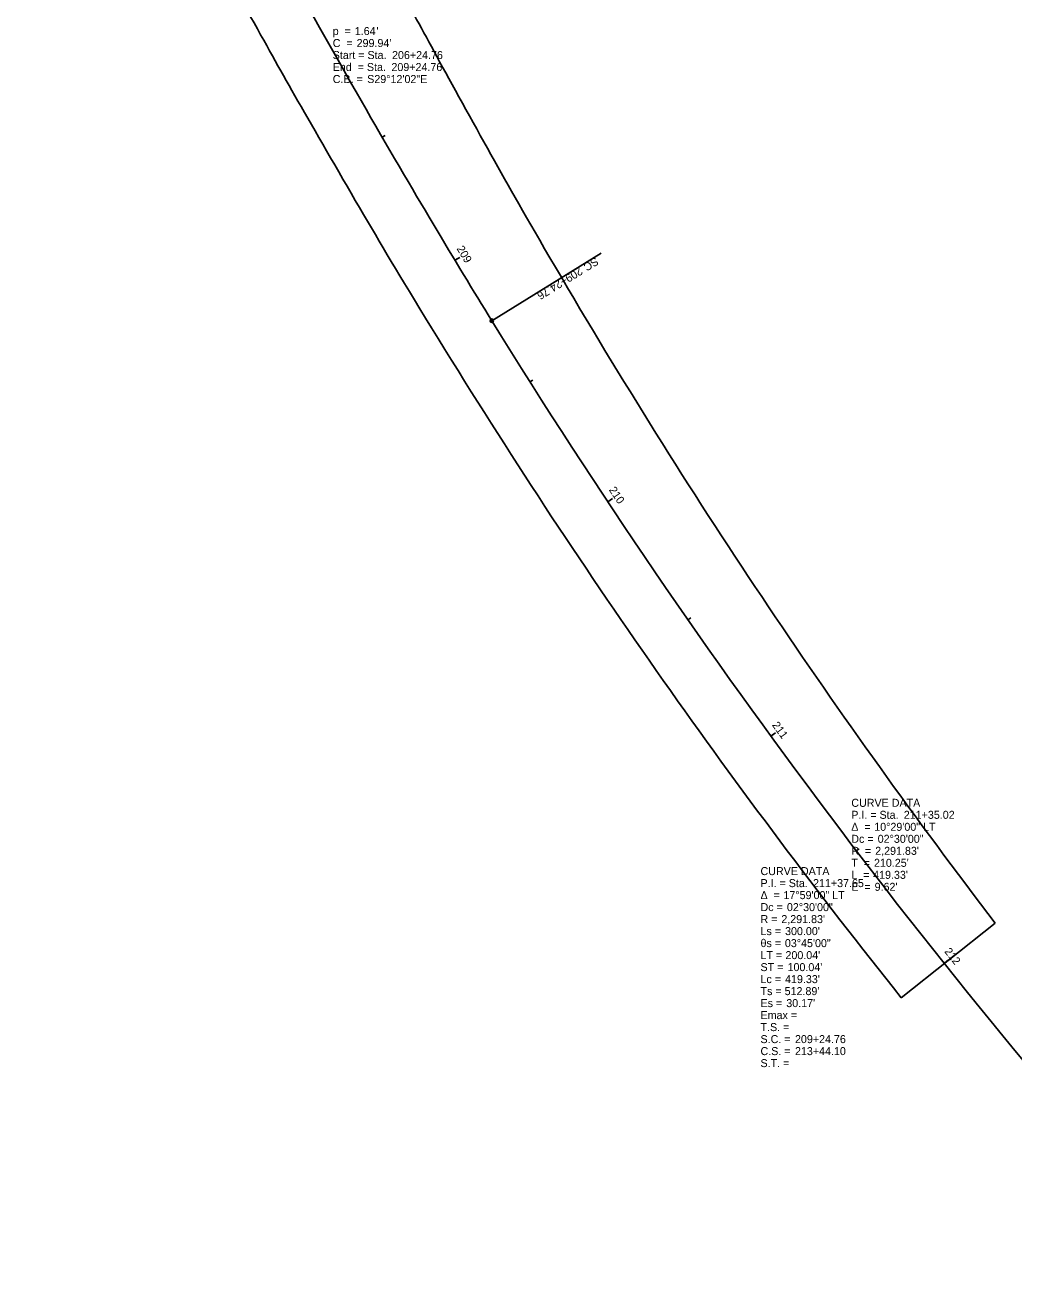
# Model space of a CAD drawing. Extents: x 2297881 to 2300632, y 559916 to 564460.
# Drawn here: x 2299974.2 to 2300320.3, y 560130.3 to 560568.5 of the extents above; entities that cross this region are included whole.
import ezdxf

# ---------------------------------------------------------------- set-up
doc = ezdxf.new("R2010")
doc.units = 0
for name, color, linetype in [('DT_P_Tie', 7, 'Continuous'), ('GE_X_Alignment', 7, 'Continuous'), ('GE_X_Alignment_1000_Cardinal_Points', 7, 'Continuous'), ('GE_X_Alignment_1000_Curve_Data', 7, 'Continuous'), ('GE_X_Alignment_1000_Stations', 7, 'Continuous'), ('GE_X_Alignment_100_Cardinal_Points', 7, 'Continuous'), ('GE_X_Alignment_100_Curve_Data', 7, 'Continuous'), ('GE_X_Alignment_100_Stations', 7, 'Continuous'), ('GE_X_Alignment_500_Cardinal_Points', 7, 'Continuous'), ('GE_X_Alignment_500_Curve_Data', 7, 'Continuous'), ('GE_X_Alignment_500_Stations', 7, 'Continuous')]:
    doc.layers.add(name, color=color, linetype=linetype)

msp = doc.modelspace()

# ---------------------------------------------------------------- linework, layer by layer
at = {"layer": 'DT_P_Tie'}
msp.add_line((2300280.82, 560228.09), (2300313.72, 560254.2), dxfattribs=at)
for centre, radius, start, end in [((2302108.04, 561623.44), 2257.08, 210.43127, 217.34714), ((2302087.44, 561669.34), 2311.08, 211.7005, 218.58141)]:
    msp.add_arc(centre, radius, start, end, dxfattribs=at)
for points in [[(2300033.82, 560720.69), (2300044.1, 560700.26), (2300054.38, 560679.88), (2300075.11, 560639.29), (2300085.55, 560619.08), (2300106.72, 560578.9), (2300117.45, 560558.93), (2300139.33, 560519.31), (2300150.48, 560499.66), (2300161.9, 560480.22)], [(2300121.16, 560454.91), (2300107.91, 560476.36), (2300095.03, 560498), (2300069.83, 560541.55), (2300057.51, 560563.46), (2300033.25, 560607.42), (2300021.31, 560629.48), (2299997.65, 560673.64), (2299985.92, 560695.75), (2299974.2, 560717.83)]]:
    msp.add_open_spline(points, degree=3, dxfattribs=at)
at = {"layer": 'GE_X_Alignment'}
msp.add_arc((2302087.44, 561669.34), 2291.83, 211.7005, 222.18383, dxfattribs=at)
msp.add_open_spline([(2299991.21, 560726.85), (2299997.06, 560715.81), (2300008.78, 560693.73), (2300032.31, 560649.61), (2300062.05, 560594.64), (2300092.7, 560540.16), (2300118.01, 560497.04), (2300130.97, 560475.66), (2300137.54, 560465.03)], degree=3, dxfattribs=at)
at = {"layer": 'GE_X_Alignment_1000_Cardinal_Points'}
msp.add_line((2300137.54, 560465.03), (2300175.82, 560488.67), dxfattribs=at)
msp.add_circle((2300137.54, 560465.03), 0.6, dxfattribs=at)
at = {"layer": 'GE_X_Alignment_1000_Stations'}
msp.add_line((2300178.12, 560401.68), (2300179.78, 560402.78), dxfattribs=at)
at = {"layer": 'GE_X_Alignment_100_Cardinal_Points'}
msp.add_line((2300137.54, 560465.03), (2300175.82, 560488.67), dxfattribs=at)
msp.add_circle((2300137.54, 560465.03), 0.6, dxfattribs=at)
at = {"layer": 'GE_X_Alignment_100_Stations'}
for p, q in [((2300099.21, 560529.22), (2300100.25, 560529.82)), ((2300124.64, 560486.17), (2300126.35, 560487.2)), ((2300150.92, 560443.63), (2300151.93, 560444.27)), ((2300178.12, 560401.68), (2300179.78, 560402.78)), ((2300206.22, 560360.33), (2300207.21, 560361.01)), ((2300235.23, 560319.6), (2300236.84, 560320.78)), ((2300265.11, 560279.52), (2300266.07, 560280.24)), ((2300295.87, 560240.09), (2300297.43, 560241.34))]:
    msp.add_line(p, q, dxfattribs=at)
at = {"layer": 'GE_X_Alignment_500_Cardinal_Points'}
msp.add_line((2300137.54, 560465.03), (2300175.82, 560488.67), dxfattribs=at)
msp.add_circle((2300137.54, 560465.03), 0.6, dxfattribs=at)
at = {"layer": 'GE_X_Alignment_500_Stations'}
for p, q in [((2300124.64, 560486.17), (2300125.66, 560486.79)), ((2300178.12, 560401.68), (2300179.78, 560402.78)), ((2300235.23, 560319.6), (2300236.2, 560320.31)), ((2300295.87, 560240.09), (2300296.8, 560240.84))]:
    msp.add_line(p, q, dxfattribs=at)

# ---------------------------------------------------------------- texts
at = {"layer": 'GE_X_Alignment_1000_Cardinal_Points'}
for s, p in [('SC', (2300173.79, 560487.36)), ('209+24.76', (2300168.24, 560483.94))]:
    msp.add_text(s, height=2.8, rotation=211.7005, dxfattribs=at).set_placement(p)
at = {"layer": 'GE_X_Alignment_1000_Curve_Data'}
for s, p in [('p  = ', (2300081.88, 560565)), ('1.64', (2300089.6, 560565)), ("'", (2300097.21, 560565)), ('C  = ', (2300081.88, 560560.8)), ("299.94'", (2300090.25, 560560.8)), ('Start = Sta. ', (2300081.88, 560556.6)), ('206+24.76', (2300102.64, 560556.6)), ('End  = Sta. ', (2300081.88, 560552.4)), ('209+24.76', (2300102.43, 560552.4)), ('C.B. = ', (2300081.88, 560548.2)), ('S29°12\'02"E', (2300093.95, 560548.2)), ('CURVE DATA', (2300263.37, 560294.89)), ('P.I. = Sta. ', (2300263.37, 560290.69)), ('211+35.02', (2300281.74, 560290.69)), ('Δ  = ', (2300263.37, 560286.49)), ('10°29\'00" LT', (2300271.4, 560286.49)), ('Dc = ', (2300263.37, 560282.29)), ('R  = ', (2300263.37, 560278.09)), ("2,291.83'", (2300271.74, 560278.09)), ('02°30\'00"', (2300272.61, 560282.29)), ('T  = ', (2300263.37, 560273.89)), ("210.25'", (2300271.31, 560273.89)), ('CURVE DATA', (2300231.6, 560270.99)), ('L  = ', (2300263.37, 560269.69)), ("419.33'", (2300271.02, 560269.69)), ('P.I. = Sta. ', (2300231.6, 560266.79)), ('211+37.65', (2300249.97, 560266.79)), ('E  = ', (2300263.37, 560265.49)), ("9.62'", (2300271.53, 560265.49)), ('Δ  = ', (2300231.6, 560262.59)), ('17°59\'00" LT', (2300239.62, 560262.59)), ('Dc = ', (2300231.6, 560258.39)), ('02°30\'00"', (2300240.84, 560258.39)), ('R = ', (2300231.6, 560254.19)), ("2,291.83'", (2300238.88, 560254.19)), ('Ls = ', (2300231.6, 560249.99)), ("300.00'", (2300240.19, 560249.99)), ('θs = ', (2300231.6, 560245.79)), ('03°45\'00"', (2300240.13, 560245.79)), ('LT = ', (2300231.6, 560241.59)), ("200.04'", (2300240.33, 560241.59)), ('ST = ', (2300231.6, 560237.39)), ("100.04'", (2300241.06, 560237.39)), ('Lc = ', (2300231.6, 560233.19)), ("419.33'", (2300240.19, 560233.19)), ('Ts = ', (2300231.6, 560228.99)), ("512.89'", (2300240.04, 560228.99)), ('Es = ', (2300231.6, 560224.79)), ("30.17'", (2300240.62, 560224.79)), ('Emax = ', (2300231.6, 560220.59)), ('T.S. = ', (2300231.6, 560216.39)), ('S.C. = ', (2300231.6, 560212.19)), ('C.S. = ', (2300231.6, 560207.99)), ('209+24.76', (2300243.66, 560212.19)), ('213+44.10', (2300243.66, 560207.99)), ('S.T. = ', (2300231.6, 560203.79))]:
    msp.add_text(s, height=2.8, dxfattribs=at).set_placement(p)
at = {"layer": 'GE_X_Alignment_1000_Stations'}
msp.add_text('210', height=2.8, rotation=303.5814, dxfattribs=at).set_placement((2300178.42, 560405.82))
at = {"layer": 'GE_X_Alignment_100_Cardinal_Points'}
for s, p in [('SC', (2300173.79, 560487.36)), ('209+24.76', (2300168.24, 560483.94))]:
    msp.add_text(s, height=2.8, rotation=211.7005, dxfattribs=at).set_placement(p)
at = {"layer": 'GE_X_Alignment_100_Curve_Data'}
for s, p in [('p  = ', (2300081.88, 560565)), ('1.64', (2300089.6, 560565)), ("'", (2300097.21, 560565)), ('C  = ', (2300081.88, 560560.8)), ("299.94'", (2300090.25, 560560.8)), ('Start = Sta. ', (2300081.88, 560556.6)), ('206+24.76', (2300102.64, 560556.6)), ('End  = Sta. ', (2300081.88, 560552.4)), ('209+24.76', (2300102.43, 560552.4)), ('C.B. = ', (2300081.88, 560548.2)), ('S29°12\'02"E', (2300093.95, 560548.2)), ('CURVE DATA', (2300263.37, 560294.89)), ('P.I. = Sta. ', (2300263.37, 560290.69)), ('211+35.02', (2300281.74, 560290.69)), ('Δ  = ', (2300263.37, 560286.49)), ('10°29\'00" LT', (2300271.4, 560286.49)), ('Dc = ', (2300263.37, 560282.29)), ('R  = ', (2300263.37, 560278.09)), ("2,291.83'", (2300271.74, 560278.09)), ('02°30\'00"', (2300272.61, 560282.29)), ('T  = ', (2300263.37, 560273.89)), ("210.25'", (2300271.31, 560273.89)), ('CURVE DATA', (2300231.6, 560270.99)), ('L  = ', (2300263.37, 560269.69)), ("419.33'", (2300271.02, 560269.69)), ('P.I. = Sta. ', (2300231.6, 560266.79)), ('211+37.65', (2300249.97, 560266.79)), ('E  = ', (2300263.37, 560265.49)), ("9.62'", (2300271.53, 560265.49)), ('Δ  = ', (2300231.6, 560262.59)), ('17°59\'00" LT', (2300239.62, 560262.59)), ('Dc = ', (2300231.6, 560258.39)), ('02°30\'00"', (2300240.84, 560258.39)), ('R = ', (2300231.6, 560254.19)), ("2,291.83'", (2300238.88, 560254.19)), ('Ls = ', (2300231.6, 560249.99)), ("300.00'", (2300240.19, 560249.99)), ('θs = ', (2300231.6, 560245.79)), ('03°45\'00"', (2300240.13, 560245.79)), ('LT = ', (2300231.6, 560241.59)), ("200.04'", (2300240.33, 560241.59)), ('ST = ', (2300231.6, 560237.39)), ("100.04'", (2300241.06, 560237.39)), ('Lc = ', (2300231.6, 560233.19)), ("419.33'", (2300240.19, 560233.19)), ('Ts = ', (2300231.6, 560228.99)), ("512.89'", (2300240.04, 560228.99)), ('Es = ', (2300231.6, 560224.79)), ("30.17'", (2300240.62, 560224.79)), ('Emax = ', (2300231.6, 560220.59)), ('T.S. = ', (2300231.6, 560216.39)), ('S.C. = ', (2300231.6, 560212.19)), ('C.S. = ', (2300231.6, 560207.99)), ('209+24.76', (2300243.66, 560212.19)), ('213+44.10', (2300243.66, 560207.99)), ('S.T. = ', (2300231.6, 560203.79))]:
    msp.add_text(s, height=2.8, dxfattribs=at).set_placement(p)
at = {"layer": 'GE_X_Alignment_100_Stations'}
for s, rotation, p in [('209', 301.107, (2300125.14, 560490.27)), ('210', 303.5814, (2300178.42, 560405.82)), ('211', 306.0814, (2300235.5, 560323.47)), ('212', 308.5814, (2300295.78, 560244.21))]:
    msp.add_text(s, height=2.8, rotation=rotation, dxfattribs=at).set_placement(p)
at = {"layer": 'GE_X_Alignment_500_Cardinal_Points'}
for s, p in [('SC', (2300173.79, 560487.36)), ('209+24.76', (2300168.24, 560483.94))]:
    msp.add_text(s, height=2.8, rotation=211.7005, dxfattribs=at).set_placement(p)
at = {"layer": 'GE_X_Alignment_500_Curve_Data'}
for s, p in [('p  = ', (2300081.88, 560565)), ('1.64', (2300089.6, 560565)), ("'", (2300097.21, 560565)), ('C  = ', (2300081.88, 560560.8)), ("299.94'", (2300090.25, 560560.8)), ('Start = Sta. ', (2300081.88, 560556.6)), ('206+24.76', (2300102.64, 560556.6)), ('End  = Sta. ', (2300081.88, 560552.4)), ('209+24.76', (2300102.43, 560552.4)), ('C.B. = ', (2300081.88, 560548.2)), ('S29°12\'02"E', (2300093.95, 560548.2)), ('CURVE DATA', (2300263.37, 560294.89)), ('P.I. = Sta. ', (2300263.37, 560290.69)), ('211+35.02', (2300281.74, 560290.69)), ('Δ  = ', (2300263.37, 560286.49)), ('10°29\'00" LT', (2300271.4, 560286.49)), ('Dc = ', (2300263.37, 560282.29)), ('R  = ', (2300263.37, 560278.09)), ("2,291.83'", (2300271.74, 560278.09)), ('02°30\'00"', (2300272.61, 560282.29)), ('T  = ', (2300263.37, 560273.89)), ("210.25'", (2300271.31, 560273.89)), ('CURVE DATA', (2300231.6, 560270.99)), ('L  = ', (2300263.37, 560269.69)), ("419.33'", (2300271.02, 560269.69)), ('P.I. = Sta. ', (2300231.6, 560266.79)), ('211+37.65', (2300249.97, 560266.79)), ('E  = ', (2300263.37, 560265.49)), ("9.62'", (2300271.53, 560265.49)), ('Δ  = ', (2300231.6, 560262.59)), ('17°59\'00" LT', (2300239.62, 560262.59)), ('Dc = ', (2300231.6, 560258.39)), ('02°30\'00"', (2300240.84, 560258.39)), ('R = ', (2300231.6, 560254.19)), ("2,291.83'", (2300238.88, 560254.19)), ('Ls = ', (2300231.6, 560249.99)), ("300.00'", (2300240.19, 560249.99)), ('θs = ', (2300231.6, 560245.79)), ('03°45\'00"', (2300240.13, 560245.79)), ('LT = ', (2300231.6, 560241.59)), ("200.04'", (2300240.33, 560241.59)), ('ST = ', (2300231.6, 560237.39)), ("100.04'", (2300241.06, 560237.39)), ('Lc = ', (2300231.6, 560233.19)), ("419.33'", (2300240.19, 560233.19)), ('Ts = ', (2300231.6, 560228.99)), ("512.89'", (2300240.04, 560228.99)), ('Es = ', (2300231.6, 560224.79)), ("30.17'", (2300240.62, 560224.79)), ('Emax = ', (2300231.6, 560220.59)), ('T.S. = ', (2300231.6, 560216.39)), ('S.C. = ', (2300231.6, 560212.19)), ('C.S. = ', (2300231.6, 560207.99)), ('209+24.76', (2300243.66, 560212.19)), ('213+44.10', (2300243.66, 560207.99)), ('S.T. = ', (2300231.6, 560203.79))]:
    msp.add_text(s, height=2.8, dxfattribs=at).set_placement(p)
at = {"layer": 'GE_X_Alignment_500_Stations'}
msp.add_text('210', height=2.8, rotation=303.5814, dxfattribs=at).set_placement((2300178.42, 560405.82))

doc.saveas('drawing.dxf')
